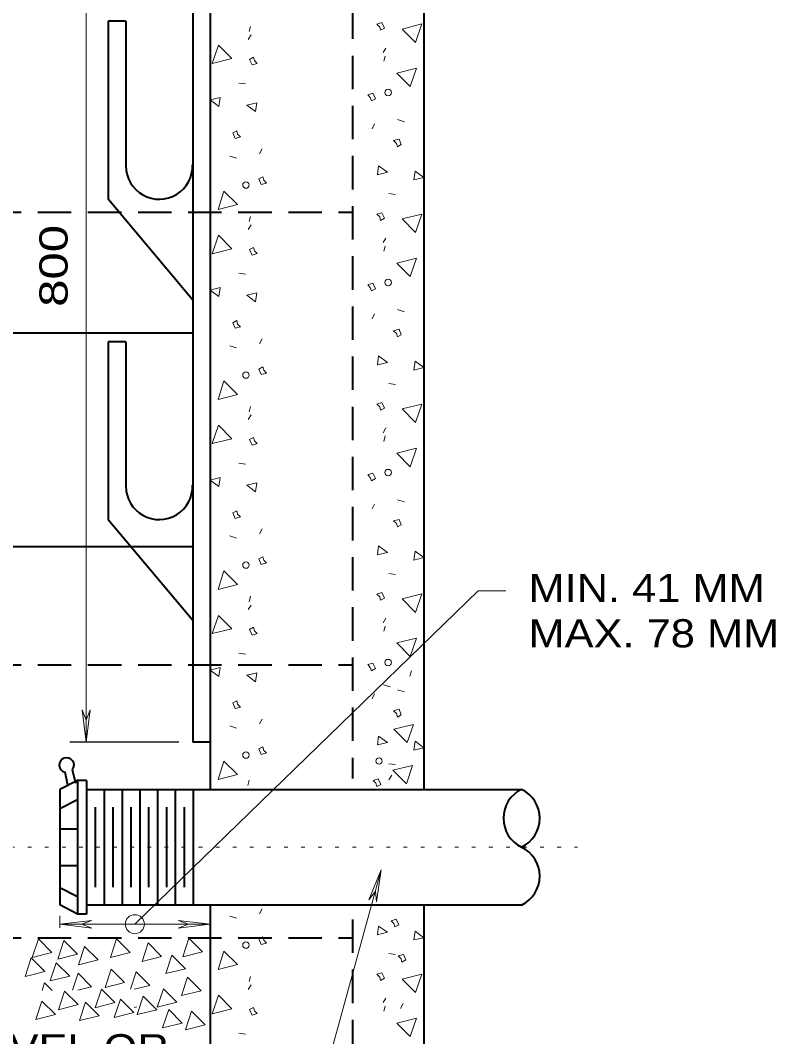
# Model space of a CAD drawing. Extents: x 312583 to 312854, y 144419 to 144597.
# Drawn here: x 312729.88 to 312750.23, y 144432.31 to 144459.67 of the extents above; entities that cross this region are included whole.
import ezdxf

# ---------------------------------------------------------------- set-up
doc = ezdxf.new("R2010")
doc.units = 0
doc.header["$LTSCALE"] = 0.3
doc.linetypes.add('DOTTED', pattern=[1.5, 0.3, -1.2])
doc.linetypes.add('MEDIUM_DASHED', pattern=[4.5, 3, -1.5])
doc.layers.add('1', color=7, linetype='Continuous', lineweight=13)

msp = doc.modelspace()

# ---------------------------------------------------------------- linework, layer by layer
at = {"layer": '1', "lineweight": 40}
for p, q in [((312735.0013, 144471.1459), (312735.0013, 144438.9689)), ((312734.5259, 144470.9082), (312734.5259, 144440.2415)), ((312732.2489, 144459.6459), (312732.2489, 144454.8542)), ((312732.7243, 144459.6459), (312732.2489, 144459.6459)), ((312732.7243, 144459.6459), (312732.7243, 144455.7512)), ((312734.5259, 144452.1402), (312732.2489, 144454.8542)), ((312718.2343, 144451.2585), (312734.5259, 144451.2585)), ((312732.2489, 144451.0209), (312732.2489, 144446.2292)), ((312732.7243, 144451.0209), (312732.2489, 144451.0209)), ((312732.7243, 144451.0209), (312732.7243, 144447.1262)), ((312734.5259, 144443.5152), (312732.2489, 144446.2292)), ((312718.2343, 144445.5085), (312734.5259, 144445.5085)), ((312735.0013, 144440.2415), (312734.5259, 144440.2415)), ((312731.1679, 144439.0839), (312731.0913, 144439.4289)), ((312731.3749, 144439.1299), (312731.2906, 144439.4979)), ((312731.4209, 144439.2065), (312731.4209, 144435.6109)), ((312731.6663, 144439.2065), (312731.6663, 144435.6109)), ((312730.9456, 144438.9689), (312730.9456, 144435.8562)), ((312731.6663, 144438.9689), (312743.3809, 144438.9689)), ((312732.1416, 144438.9689), (312732.1416, 144435.8562)), ((312732.6246, 144438.9689), (312732.6246, 144435.8562)), ((312733.0999, 144438.9689), (312733.0999, 144435.8562)), ((312733.5829, 144438.9689), (312733.5829, 144435.8562)), ((312734.0583, 144438.9689), (312734.0583, 144435.8562)), ((312734.5413, 144438.9689), (312734.5413, 144435.8562)), ((312731.4209, 144438.6852), (312730.9456, 144438.4475)), ((312731.9039, 144438.4859), (312731.9039, 144436.3315)), ((312732.3793, 144438.4859), (312732.3793, 144436.3315)), ((312732.8623, 144438.4859), (312732.8623, 144436.3315)), ((312733.3376, 144438.4859), (312733.3376, 144436.3315)), ((312733.8206, 144438.4859), (312733.8206, 144436.3315)), ((312734.2959, 144438.4859), (312734.2959, 144436.3315)), ((312730.9456, 144437.9032), (312731.4209, 144437.9032)), ((312730.9456, 144436.9219), (312731.4209, 144436.9219)), ((312731.4209, 144436.0785), (312730.9456, 144436.3162)), ((312731.6663, 144435.8562), (312743.3809, 144435.8562)), ((312735.0013, 144435.8562), (312735.0013, 144429.2169)), ((312740.7513, 144435.8562), (312740.7513, 144429.2169))]:
    msp.add_line(p, q, dxfattribs=at)
at = {"layer": '1'}
for p, q in [((312731.6586, 144440.2415), (312731.6586, 144469.2062)), ((312736.0209, 144459.1552), (312736.1053, 144459.2779)), ((312736.0439, 144459.3699), (312736.0823, 144459.5079)), ((312739.7316, 144458.9252), (312739.6549, 144458.8025)), ((312739.7086, 144458.7105), (312739.6703, 144458.5725)), ((312735.7679, 144457.9822), (312735.9443, 144457.9592)), ((312739.4249, 144456.8859), (312739.3559, 144456.7555)), ((312740.2299, 144456.9395), (312740.0459, 144457.0009)), ((312735.5226, 144456.0195), (312735.7066, 144455.9659)), ((312736.3276, 144456.0809), (312736.3966, 144456.2112)), ((312739.9846, 144454.9845), (312739.8083, 144455.0075)), ((312736.0439, 144454.2562), (312736.0823, 144454.3942)), ((312736.0209, 144454.0415), (312736.1053, 144454.1642)), ((312739.7316, 144453.8115), (312739.6549, 144453.6889)), ((312739.7086, 144453.5969), (312739.6703, 144453.4589)), ((312735.7679, 144452.8685), (312735.9443, 144452.8379)), ((312740.2299, 144451.8259), (312740.0459, 144451.8872)), ((312739.4249, 144451.7722), (312739.3559, 144451.6342)), ((312736.3276, 144450.9672), (312736.3966, 144451.0975)), ((312735.5226, 144450.9059), (312735.7066, 144450.8522)), ((312739.9846, 144449.8709), (312739.8083, 144449.8939)), ((312736.0439, 144449.1349), (312736.0823, 144449.2805)), ((312736.0209, 144448.9279), (312736.1053, 144449.0505)), ((312739.7316, 144448.6979), (312739.6549, 144448.5675)), ((312739.7086, 144448.4832), (312739.6703, 144448.3375)), ((312735.7679, 144447.7472), (312735.9443, 144447.7242)), ((312740.2299, 144446.7122), (312740.0459, 144446.7659)), ((312739.4249, 144446.6509), (312739.3559, 144446.5205)), ((312736.3276, 144445.8459), (312736.3966, 144445.9839)), ((312735.5226, 144445.7922), (312735.7066, 144445.7309)), ((312739.9846, 144444.7495), (312739.8083, 144444.7802)), ((312732.9696, 144435.3349), (312742.2184, 144444.3174)), ((312742.9611, 144444.3174), (312742.2184, 144444.3174)), ((312736.0439, 144444.0212), (312736.0823, 144444.1669)), ((312736.0209, 144443.8065), (312736.1053, 144443.9292)), ((312739.7316, 144443.5765), (312739.6549, 144443.4539)), ((312739.7086, 144443.3619), (312739.6703, 144443.2239)), ((312735.7679, 144442.6335), (312735.9443, 144442.6105)), ((312740.4216, 144442.1582), (312740.3756, 144442.0125)), ((312739.8466, 144441.7289), (312739.6626, 144441.7825)), ((312739.4249, 144441.5372), (312739.3559, 144441.4069)), ((312740.2299, 144441.5985), (312740.0459, 144441.6522)), ((312731.5513, 144441.1079), (312731.6586, 144440.8319)), ((312731.6586, 144440.2415), (312731.5513, 144441.1079)), ((312731.7659, 144441.1079), (312731.6586, 144440.8319)), ((312731.6586, 144440.2415), (312731.7659, 144441.1079)), ((312735.5226, 144440.6785), (312735.7066, 144440.6172)), ((312736.3276, 144440.7322), (312736.3966, 144440.8625)), ((312739.9846, 144439.6359), (312739.8083, 144439.6589)), ((312739.8926, 144439.3522), (312739.8083, 144439.2295)), ((312736.0133, 144439.0762), (312736.0516, 144439.2142)), ((312739.6013, 144436.7992), (312737.1556, 144427.8905)), ((312739.6013, 144436.7992), (312739.2716, 144435.9942)), ((312739.6013, 144436.7992), (312739.4786, 144435.9405)), ((312739.2716, 144435.9942), (312739.4479, 144436.2319)), ((312739.4786, 144435.9405), (312739.4479, 144436.2319)), ((312736.3276, 144435.6185), (312736.3966, 144435.7489)), ((312730.9456, 144435.5649), (312730.9456, 144435.2429)), ((312735.5226, 144435.5572), (312735.7066, 144435.5035)), ((312730.9456, 144435.3349), (312731.8119, 144435.4422)), ((312735.0013, 144435.3349), (312730.9456, 144435.3349)), ((312730.9456, 144435.3349), (312731.8119, 144435.2275)), ((312731.8119, 144435.4422), (312731.5359, 144435.3349)), ((312731.8119, 144435.2275), (312731.5359, 144435.3349)), ((312734.1349, 144435.4422), (312734.4109, 144435.3349)), ((312735.0013, 144435.3349), (312734.1349, 144435.4422)), ((312734.1349, 144435.2275), (312734.4109, 144435.3349)), ((312735.0013, 144435.3349), (312734.1349, 144435.2275)), ((312739.9846, 144434.5222), (312739.8083, 144434.5452)), ((312736.0439, 144433.7939), (312736.0823, 144433.9319)), ((312731.4363, 144433.5639), (312731.8043, 144433.6559)), ((312732.9466, 144433.5869), (312733.3683, 144433.6865)), ((312736.0209, 144433.5792), (312736.1053, 144433.7019)), ((312739.7316, 144433.3492), (312739.6549, 144433.2265)), ((312732.9466, 144433.0962), (312733.0233, 144433.1115)), ((312739.7086, 144433.1345), (312739.6703, 144432.9965)), ((312740.1916, 144433.2035), (312740.1226, 144433.0732)), ((312735.7679, 144432.4062), (312735.9443, 144432.3755))]:
    msp.add_line(p, q, dxfattribs=at)
at = {"layer": '1', "linetype": 'MEDIUM_DASHED', "lineweight": 40}
for p, q in [((312738.8346, 144468.1712), (312738.8346, 144439.2602)), ((312699.3053, 144454.5092), (312738.8346, 144454.5092)), ((312699.3053, 144442.3192), (312738.8346, 144442.3192)), ((312738.8346, 144435.4652), (312738.8346, 144432.0919)), ((312699.3053, 144434.9669), (312738.8346, 144434.9669))]:
    msp.add_line(p, q, dxfattribs=at)
at = {"layer": '1', "lineweight": 25}
msp.add_line((312734.1503, 144440.2415), (312731.2216, 144440.2415), dxfattribs=at)
at = {"layer": '1', "linetype": 'DOTTED'}
msp.add_line((312729.1669, 144437.4125), (312744.8913, 144437.4125), dxfattribs=at)
at = {"layer": '1', "lineweight": 40}
for points in [[(312740.7513, 144468.5085), (312740.7513, 144461.6392), (312740.7513, 144438.9689)], [(312731.6663, 144439.2065), (312731.4209, 144439.2065), (312730.9456, 144438.9689)], [(312731.6663, 144435.6109), (312731.4209, 144435.6109), (312730.9456, 144435.8562)]]:
    msp.add_lwpolyline(points, dxfattribs=at)
at = {"layer": '1'}
for points in [[(312739.5629, 144459.4925), (312739.5859, 144459.4082), (312739.6933, 144459.4619), (312739.6243, 144459.6152), (312739.4863, 144459.5692)], [(312740.1686, 144459.4389), (312740.5289, 144459.0785), (312740.6976, 144459.5769)], [(312735.5839, 144458.6415), (312735.2236, 144459.0019), (312735.0549, 144458.5112)], [(312736.1896, 144458.5879), (312736.1666, 144458.6799), (312736.0593, 144458.6185), (312736.1283, 144458.4729), (312736.2663, 144458.5112)], [(312740.0229, 144458.2505), (312740.3833, 144457.8902), (312740.5519, 144458.3809)], [(312739.3099, 144457.5989), (312739.3406, 144457.5069), (312739.4479, 144457.5605), (312739.3789, 144457.7139), (312739.2409, 144457.6679)], [(312735.2313, 144457.3535), (312735.2696, 144457.5912), (312735.0013, 144457.5299)], [(312736.2203, 144457.2155), (312736.2509, 144457.4532), (312735.9826, 144457.3842)], [(312735.7373, 144456.6099), (312735.7143, 144456.7019), (312735.6069, 144456.6405), (312735.6683, 144456.4949), (312735.8139, 144456.5332)], [(312740.0153, 144456.3569), (312740.0383, 144456.2649), (312740.1456, 144456.3262), (312740.0843, 144456.4719), (312739.9386, 144456.4335)], [(312739.5323, 144455.7512), (312739.5016, 144455.5135), (312739.7699, 144455.5825)], [(312736.4426, 144455.3679), (312736.4119, 144455.4599), (312736.3046, 144455.4062), (312736.3736, 144455.2529), (312736.5116, 144455.2912)], [(312740.5213, 144455.6132), (312740.4829, 144455.3755), (312740.7513, 144455.4369)], [(312735.7373, 144454.7162), (312735.3693, 144455.0765), (312735.2083, 144454.5782)], [(312739.5629, 144454.3789), (312739.5859, 144454.2869), (312739.6933, 144454.3482), (312739.6243, 144454.4939), (312739.4863, 144454.4555)], [(312740.1686, 144454.3252), (312740.5289, 144453.9649), (312740.6976, 144454.4555)], [(312735.5839, 144453.5202), (312735.2236, 144453.8882), (312735.0549, 144453.3899)], [(312736.1896, 144453.4665), (312736.1666, 144453.5585), (312736.0593, 144453.5049), (312736.1283, 144453.3515), (312736.2663, 144453.3975)], [(312740.0229, 144453.1369), (312740.3833, 144452.7765), (312740.5519, 144453.2672)], [(312735.2313, 144452.2399), (312735.2696, 144452.4775), (312735.0013, 144452.4085)], [(312739.3099, 144452.4775), (312739.3406, 144452.3932), (312739.4479, 144452.4469), (312739.3789, 144452.5925), (312739.2409, 144452.5542)], [(312736.2203, 144452.0942), (312736.2509, 144452.3395), (312735.9826, 144452.2705)], [(312735.7373, 144451.4962), (312735.7143, 144451.5882), (312735.6069, 144451.5269), (312735.6683, 144451.3812), (312735.8139, 144451.4195)], [(312740.0153, 144451.2432), (312740.0383, 144451.1512), (312740.1456, 144451.2049), (312740.0843, 144451.3582), (312739.9386, 144451.3122)], [(312739.5323, 144450.6375), (312739.5016, 144450.3999), (312739.7699, 144450.4612)], [(312740.5213, 144450.4995), (312740.4829, 144450.2542), (312740.7513, 144450.3232)], [(312736.4426, 144450.2542), (312736.4119, 144450.3462), (312736.3046, 144450.2849), (312736.3736, 144450.1392), (312736.5116, 144450.1775)], [(312735.7373, 144449.5949), (312735.3693, 144449.9629), (312735.2083, 144449.4645)], [(312739.5629, 144449.2652), (312739.5859, 144449.1732), (312739.6933, 144449.2345), (312739.6243, 144449.3802), (312739.4863, 144449.3419)], [(312740.1686, 144449.2115), (312740.5289, 144448.8435), (312740.6976, 144449.3419)], [(312735.5839, 144448.4065), (312735.2236, 144448.7745), (312735.0549, 144448.2762)], [(312736.1896, 144448.3529), (312736.1666, 144448.4449), (312736.0593, 144448.3912), (312736.1283, 144448.2379), (312736.2663, 144448.2762)], [(312740.0229, 144448.0232), (312740.3833, 144447.6552), (312740.5519, 144448.1535)], [(312735.2313, 144447.1185), (312735.2696, 144447.3639), (312735.0013, 144447.2949)], [(312736.2203, 144446.9805), (312736.2509, 144447.2182), (312735.9826, 144447.1569)], [(312739.3099, 144447.3639), (312739.3406, 144447.2719), (312739.4479, 144447.3332), (312739.3789, 144447.4789), (312739.2409, 144447.4405)], [(312735.7373, 144446.3749), (312735.7143, 144446.4669), (312735.6069, 144446.4132), (312735.6683, 144446.2599), (312735.8139, 144446.3059)], [(312740.0153, 144446.1219), (312740.0383, 144446.0375), (312740.1456, 144446.0912), (312740.0843, 144446.2369), (312739.9386, 144446.1985)], [(312739.5323, 144445.5239), (312739.5016, 144445.2785), (312739.7699, 144445.3475)], [(312740.5213, 144445.3782), (312740.4829, 144445.1405), (312740.7513, 144445.2095)], [(312736.4426, 144445.1405), (312736.4119, 144445.2325), (312736.3046, 144445.1712), (312736.3736, 144445.0255), (312736.5116, 144445.0639)], [(312735.7373, 144444.4812), (312735.3693, 144444.8492), (312735.2083, 144444.3509)], [(312739.5629, 144444.1515), (312739.5859, 144444.0595), (312739.6933, 144444.1132), (312739.6243, 144444.2665), (312739.4863, 144444.2205)], [(312740.1686, 144444.0979), (312740.5289, 144443.7299), (312740.6976, 144444.2282)], [(312735.5839, 144443.2929), (312735.2236, 144443.6532), (312735.0549, 144443.1625)], [(312736.1896, 144443.2392), (312736.1666, 144443.3312), (312736.0593, 144443.2699), (312736.1283, 144443.1242), (312736.2663, 144443.1625)], [(312740.0229, 144442.9095), (312740.3833, 144442.5415), (312740.5519, 144443.0399)], [(312739.3099, 144442.2502), (312739.3406, 144442.1582), (312739.4479, 144442.2195), (312739.3789, 144442.3652), (312739.2409, 144442.3269)], [(312735.2313, 144442.0049), (312735.2696, 144442.2502), (312735.0013, 144442.1812)], [(312736.2203, 144441.8669), (312736.2509, 144442.1045), (312735.9826, 144442.0432)], [(312735.7373, 144441.2612), (312735.7143, 144441.3532), (312735.6069, 144441.2995), (312735.6683, 144441.1462), (312735.8139, 144441.1845)], [(312740.0153, 144441.0082), (312740.0383, 144440.9162), (312740.1456, 144440.9775), (312740.0843, 144441.1232), (312739.9386, 144441.0849)], [(312739.9463, 144440.5865), (312740.3066, 144440.2262), (312740.4753, 144440.7169)], [(312739.5323, 144440.4025), (312739.5016, 144440.1649), (312739.7699, 144440.2339)], [(312736.4426, 144440.0192), (312736.4119, 144440.1112), (312736.3046, 144440.0575), (312736.3736, 144439.9042), (312736.5116, 144439.9502)], [(312740.5213, 144440.2645), (312740.4829, 144440.0269), (312740.7513, 144440.0882)], [(312735.7373, 144439.3675), (312735.3693, 144439.7279), (312735.2083, 144439.2372)], [(312739.9156, 144439.4825), (312740.2836, 144439.1145), (312740.4446, 144439.6129)], [(312739.4633, 144439.1375), (312739.4863, 144439.0455), (312739.5936, 144439.0992), (312739.5246, 144439.2525), (312739.3866, 144439.2065)], [(312739.9463, 144435.3579), (312739.9693, 144435.2659), (312740.0766, 144435.3195), (312740.0076, 144435.4729), (312739.8696, 144435.4269)], [(312739.5323, 144435.2889), (312739.5016, 144435.0512), (312739.7699, 144435.1202)], [(312730.7309, 144434.5759), (312730.3706, 144434.9439), (312730.2019, 144434.4455)], [(312732.8393, 144434.5759), (312732.4713, 144434.9439), (312732.3103, 144434.4455)], [(312734.7866, 144434.5912), (312734.4186, 144434.9592), (312734.2576, 144434.4609)], [(312736.4426, 144434.9055), (312736.4119, 144434.9975), (312736.3046, 144434.9439), (312736.3736, 144434.7905), (312736.5116, 144434.8289)], [(312740.5213, 144435.1509), (312740.4829, 144434.9132), (312740.7513, 144434.9745)], [(312731.4209, 144434.5299), (312731.0529, 144434.8979), (312730.8919, 144434.3995)], [(312731.9806, 144434.3765), (312731.6126, 144434.7369), (312731.4516, 144434.2462)], [(312733.6903, 144434.4685), (312733.3299, 144434.8365), (312733.1613, 144434.3382)], [(312730.5469, 144434.0622), (312730.1789, 144434.4302), (312730.0179, 144433.9319)], [(312734.3343, 144434.1389), (312733.9663, 144434.5069), (312733.8053, 144434.0085)], [(312735.7373, 144434.2539), (312735.3693, 144434.6142), (312735.2083, 144434.1159)], [(312740.1379, 144434.4072), (312740.1609, 144434.3152), (312740.2683, 144434.3765), (312740.2069, 144434.5222), (312740.0613, 144434.4839)], [(312731.2139, 144433.9395), (312730.8536, 144434.2999), (312730.6849, 144433.8092)], [(312732.6936, 144433.7709), (312732.3333, 144434.1312), (312732.1646, 144433.6329)], [(312734.7559, 144433.5485), (312734.3879, 144433.9165), (312734.2269, 144433.4182)], [(312739.5629, 144433.9165), (312739.5859, 144433.8245), (312739.6933, 144433.8859), (312739.6243, 144434.0315), (312739.4863, 144433.9932)], [(312740.1686, 144433.8629), (312740.5289, 144433.5025), (312740.6976, 144433.9932)], [(312731.4439, 144433.1729), (312731.0759, 144433.5332), (312730.9149, 144433.0349)], [(312732.4329, 144433.2265), (312732.0726, 144433.5869), (312731.9039, 144433.0885)], [(312734.0966, 144433.2419), (312733.7363, 144433.6022), (312733.5676, 144433.1039)], [(312730.8306, 144432.9045), (312730.4626, 144433.2649), (312730.3016, 144432.7742)], [(312732.9389, 144432.9582), (312732.5786, 144433.3185), (312732.4099, 144432.8279)], [(312733.5599, 144433.0349), (312733.1919, 144433.4029), (312733.0309, 144432.9045)], [(312735.5839, 144433.0579), (312735.2236, 144433.4259), (312735.0549, 144432.9275)], [(312732.0036, 144432.8739), (312731.6433, 144433.2419), (312731.4746, 144432.7435)], [(312734.2423, 144432.6745), (312733.8819, 144433.0425), (312733.7133, 144432.5442)], [(312734.8633, 144432.6285), (312734.4953, 144432.9965), (312734.3343, 144432.4982)], [(312736.1896, 144433.0042), (312736.1666, 144433.0962), (312736.0593, 144433.0425), (312736.1283, 144432.8892), (312736.2663, 144432.9352)], [(312740.0229, 144432.6745), (312740.3833, 144432.3142), (312740.5519, 144432.8049)]]:
    msp.add_lwpolyline(points, close=True, dxfattribs=at)
for points in [[(312731.8043, 144433.6559), (312731.4439, 144434.0239), (312731.2906, 144433.5639)], [(312733.3683, 144433.6865), (312733.0003, 144434.0545), (312732.8469, 144433.5869)], [(312730.7386, 144433.5562), (312730.5393, 144433.7555), (312730.4703, 144433.5562)]]:
    msp.add_lwpolyline(points, dxfattribs=at)
for centre, radius in [((312739.7916, 144457.729), 0.0865), ((312735.9609, 144455.2379), 0.0865), ((312739.7916, 144452.6135), 0.0865), ((312735.9609, 144450.1223), 0.0865), ((312739.7916, 144447.4979), 0.0865), ((312735.9609, 144445.0067), 0.0865), ((312739.7916, 144442.3823), 0.0865), ((312735.9609, 144439.8911), 0.0865), ((312739.5444, 144439.7315), 0.0865), ((312732.9686, 144435.3387), 0.2555), ((312735.9609, 144434.7755), 0.0865)]:
    msp.add_circle(centre, radius, dxfattribs=at)
at = {"layer": '1', "lineweight": 40}
for centre, radius, start, end in [((312733.6241, 144455.7546), 0.8984, 180.03057, 1.87136), ((312733.6241, 144447.1296), 0.8984, 180.03057, 1.87136), ((312731.1315, 144439.6225), 0.1983, 321.8583, 257.71168), ((312743.7592, 144438.1902), 0.8644, 115.73681, 244.26319), ((312743.0085, 144438.1902), 0.8644, 295.73681, 64.26319), ((312743.0085, 144436.6329), 0.8644, 295.73681, 64.26319)]:
    msp.add_arc(centre, radius, start, end, dxfattribs=at)

# ---------------------------------------------------------------- texts
at = {"layer": '1', "width": 1.3}
msp.add_text('800 ', height=0.76, rotation=90, dxfattribs=at).set_placement((312731.1576, 144451.9599))
at = {"layer": '1', "width": 1.15}
for s, p in [('MIN. 41 MM', (312743.5704, 144444.0097)), ('MAX. 78 MM', (312743.5704, 144442.7897)), ('19 MM GRAVEL OR', (312723.1664, 144431.6176))]:
    msp.add_text(s, height=0.76, dxfattribs=at).set_placement(p)

doc.saveas('drawing.dxf')
